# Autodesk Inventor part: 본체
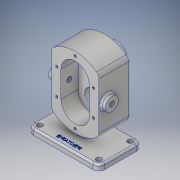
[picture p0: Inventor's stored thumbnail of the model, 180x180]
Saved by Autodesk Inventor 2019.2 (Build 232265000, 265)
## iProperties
Created: 2019-03
Part Number: 본체
Material: 알루미늄 6061
Document SubType Name: Modeling
Designer: User
Density: 2.7 g/cm^3
Appearance: 알루미늄 - 평지
Mass: 1187.12 g
Surface Area: 719.257 cm^2
Volume: 439.673 cm^3
Author: User
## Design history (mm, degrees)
sketch "스케치1"
  geometry: L1 (60, 36.5)-(-60, 36.5); L2 (-60, 36.5)-(-60, -36.5); L3 (-60, -36.5)-(60, -36.5); L4 (60, -36.5)-(60, 36.5); L5 (60, 36.5)-(-60, -36.5); L6 (-60, 36.5)-(60, -36.5); 1 further point
  constraints: 12 end point, 2 midpoint, 2 parallel, 1 horizontal, 1 perpendicular
  dimensions: "d0" = 73 distance between parallel lines of L1 L3; "d1" = 120 distance of L1.start L1.end
extrude "돌출1" new body sketch "스케치1" distance "d2" = 10; taper "d3" = 0 deg
sketch "스케치2"
  geometry: L1 (-6, 36.5)-(6, 36.5); L2 (6, 36.5)-(6, -6.5); L3 (6, -6.5)-(-6, -6.5); L4 (-6, -6.5)-(-6, 36.5); L5 (60, 36.5)-(-60, 36.5) reference; 1 further point
  constraints: 8 end point, 2 parallel, 1 collinear, 1 horizontal, 1 perpendicular
  dimensions: "d4" = 12 distance between parallel lines of L2 L4; "d5" = 6 distance from line of point (0, 0) L4; "d6" = 43 distance between parallel lines of L5 L3
extrude "돌출2" join sketch "스케치2" distance "d7" = 68; taper "d8" = 0 deg
sketch "스케치3"
  geometry: L1 (0, 0)-(120, 0) reference; L2 (100, 122.721)-(100, 33.279); L3 (20, 33.279)-(20, 122.721); L4 (-28, 78)-(188, 78); L5 (54, 78)-(66, 78) reference; A1 r 60 centre (60, 78) between (100, 122.721) and (20, 122.721); A2 r 60 centre (60, 78) between (20, 33.279) and (100, 33.279); 2 further points
  constraints: 6 end point, 4 point on circle, 2 centre point, 2 midpoint, 1 horizontal, 1 parallel, 1 perpendicular
  dimensions: "d10" = 78 distance between parallel lines of L1 L4; "d12" = 80 distance between parallel lines of L2 L3; "d13" = 40 distance from line of A1.centre L3; "d14" = 60 radius of A1; "d15" = 60 radius of A2
extrude "돌출3" join sketch "스케치3" distance "d16" = 53; taper "d17" = 0 deg
sketch "스케치4"
  geometry: L1 (0, 0)-(120, 0) reference; C1 r 19 at (60, 100); 2 further points
  constraints: 1 centre point, 1 midpoint, 1 vertical alignment
  dimensions: "d18" = 38 diameter of C1; "d47" = 100 distance from line of L1 C1.centre
extrude "돌출4" join sketch "스케치4" distance "d19" = 17; taper "d20" = 0 deg
sketch "스케치5"
  geometry: L1 (-60, 100)-(-60, 56); L2 (-84, 100)-(-84, 56); L3 (-36, 56)-(-36, 100); L4 (-120, 0)-(0, 0) reference; L5 (-135, 78)-(56, 78); A1 r 24 centre (-60, 100) between (-36, 100) and (-84, 100); A2 r 24 centre (-60, 56) between (-84, 56) and (-36, 56); 3 further points
  constraints: 10 end point, 4 point on circle, 4 tangent, 2 centre point, 2 midpoint, 1 horizontal, 1 parallel, 1 point on line, 1 vertical, 1 vertical alignment
  dimensions: "d21" = 24 radius of A1; "d22" = 44 distance of L1.start L1.end; "d23" = 78 distance between parallel lines of L4 L5
extrude "돌출5" cut sketch "스케치5" distance "d24" = 29; taper "d25" = 0 deg
sketch "스케치6"
  geometry: 1 further point
sketch "스케치7"
  geometry: A1 r 24 centre (-60, 56) between (-84, 56) and (-36, 56) reference; 2 further points
  constraints: 1 coincident
hole "구멍1" sketch "스케치7" at (-60, 56) diameter "d26" = 25; stored, may be unused: countersink angle "d30" = 90 deg, drill point angle "d32" = 0 deg; dims "d27" = 20, "d28" = 4, "d29" = 2, "d31" = 15
sketch "스케치8"
  geometry: A1 r 24 centre (-60, 100) between (-36, 100) and (-84, 100) reference; 2 further points
  constraints: 1 coincident
hole "구멍2" sketch "스케치8" at (-60, 100) diameter "d33" = 25; stored, may be unused: countersink angle "d37" = 90 deg, drill point angle "d39" = 0 deg; dims "d34" = 20, "d35" = 4, "d36" = 2, "d38" = 15
sketch "스케치9"
  geometry: C1 r 12.5 at (0, 0) reference; 2 further points
  constraints: 1 coincident
hole "구멍3" sketch "스케치9" at (0, 0) diameter "d40" = 17; stored, may be unused: countersink angle "d44" = 90 deg, drill point angle "d46" = 0 deg; dims "d41" = 20, "d42" = 4, "d43" = 2, "d45" = 15
sketch "스케치10"
  geometry: C1 r 12.5 at (0, 0) reference; C2 r 14 at (0, 0); 1 further point
  constraints: 1 centre point, 1 coincident
  dimensions: "d48" = 28 diameter of C2
extrude "돌출6" cut sketch "스케치10" distance "d49" = 7.3; taper "d50" = 0 deg
chamfer "모따기1" distance "d51" = 0.7; stored, may be unused: second distance "d52" = 2, angle "d53" = 30 deg
fillet "모깎기1" dims "d54" = 0.5
sketch "스케치11"
  geometry: L1 (-73, -33.279)-(0, -33.279) reference; L2 (-53, 0)-(-53, 89.443) reference; C1 r 11 at (-39, 44.721); 1 further point
  constraints: 1 centre point
  dimensions: "d55" = 22 diameter of C1; "d56" = 78 distance from line of L1 C1.centre; "d57" = 14 distance from line of L2 C1.centre
extrude "돌출7" join sketch "스케치11" distance "d58" = 8; taper "d59" = 0 deg
sketch "스케치12"
  geometry: C1 r 11 at (0, 0) reference; 2 further points
  constraints: 1 coincident
hole "구멍4" sketch "스케치12" at (0, 0) diameter "d60" = 8.376; stored, may be unused: countersink angle "d64" = 90 deg, drill point angle "d66" = 0 deg; dims "d61" = 100, "d62" = 4, "d63" = 2, "d65" = 27.3
sketch "스케치13"
  geometry: L1 (-120, 0)-(0, 0) reference; L2 (-126, 78)-(26, 78); C1 r 5.385 at (-60, 131); C2 r 8.5 at (-60, 100) reference; C3 r 5.385 at (-60, 25); 2 further points
  constraints: 2 centre point, 2 end point, 1 horizontal, 1 midpoint, 1 symmetric about line, 1 vertical alignment, 1 other
  dimensions: "d67" = 78 distance between parallel lines of L1 L2; "d69" = 31 distance of C1.centre C2.centre; "d70" = 10.77033 diameter of C1
hole "구멍5" sketch "스케치13" at (-60, 131), (-60, 25) diameter "d71" = 4.134; stored, may be unused: countersink angle "d75" = 90 deg, drill point angle "d77" = 118 deg; dims "d72" = 10, "d73" = 4, "d74" = 2, "d76" = 12
sketch "스케치14"
  geometry: L1 (-153, 78)-(62, 78); L2 (-120, 0)-(0, 0) reference; L3 (-60, -27.6)-(-60, 165.6) reference; C1 r 6.403 at (-91, 100); C2 r 6 at (-29, 100); C3 r 6 at (-29, 56); C4 r 6.403 at (-91, 56); 1 further point
  constraints: 4 centre point, 2 end point, 2 symmetric about line, 1 horizontal, 1 horizontal alignment, 2 other
  dimensions: "d78" = 78 distance between parallel lines of L2 L1; "d79" = 22 distance from line of L1 C2.centre; "d80" = 31 distance from line of C2.centre L3; "d81" = 31 distance from line of L3 C1.centre; "d82" = 12 diameter of C2; "d83" = 12.80625 diameter of C1
hole "구멍6" sketch "스케치14" at (-91, 100), (-91, 56), (-29, 56), (-29, 100) diameter "d84" = 4.134; stored, may be unused: countersink angle "d88" = 90 deg, drill point angle "d90" = 118 deg; dims "d85" = 10, "d86" = 4, "d87" = 2, "d89" = 12
sketch "스케치15"
  geometry: L1 (-60, 36.5)-(-60, -36.5) reference; L2 (-60, -36.5)-(60, -36.5) reference; C1 r 4.5 at (-50, -26.5); 1 further point
  constraints: 1 centre point
  dimensions: "d91" = 9 diameter of C1; "d92" = 10 distance from line of L1 C1.centre; "d93" = 10 distance from line of L2 C1.centre
extrude "돌출8" cut sketch "스케치15" extent not by distance; stored distance "d94" = 8; taper "d95" = 0 deg
fillet "모깎기2" dims "d96" = 10
fillet "모깎기3" dims "d97" = 10
fillet "모깎기7" dims "d101" = 3
chamfer "모따기2" distance "d102" = 1; stored, may be unused: second distance "d103" = 2, angle "d104" = 30 deg
fillet "모깎기8" dims "d105" = 3
fillet "모깎기9" dims "d106" = 3
fillet "모깎기10" dims "d107" = 3
fillet "모깎기11" dims "d108" = 3
sketch "스케치16"
  geometry: L1 (-60, 26.5)-(-60, -26.5) reference; L2 (-50, -36.5)-(50, -36.5) reference; 2 further points
  constraints: 1 other
  dimensions: "d109" = 60 distance from line of L1 point (0, -26.5); "d110" = 10 distance from line of L2 point (0, -26.5)
feature "엠보싱1" sketch "스케치16" dims "d0" = 73, "d1" = 120, "d111" = 0.5, "d112" = 0
node "솔리드1"
mirror "미러1"
mirror "미러2"
mirror "미러3"
